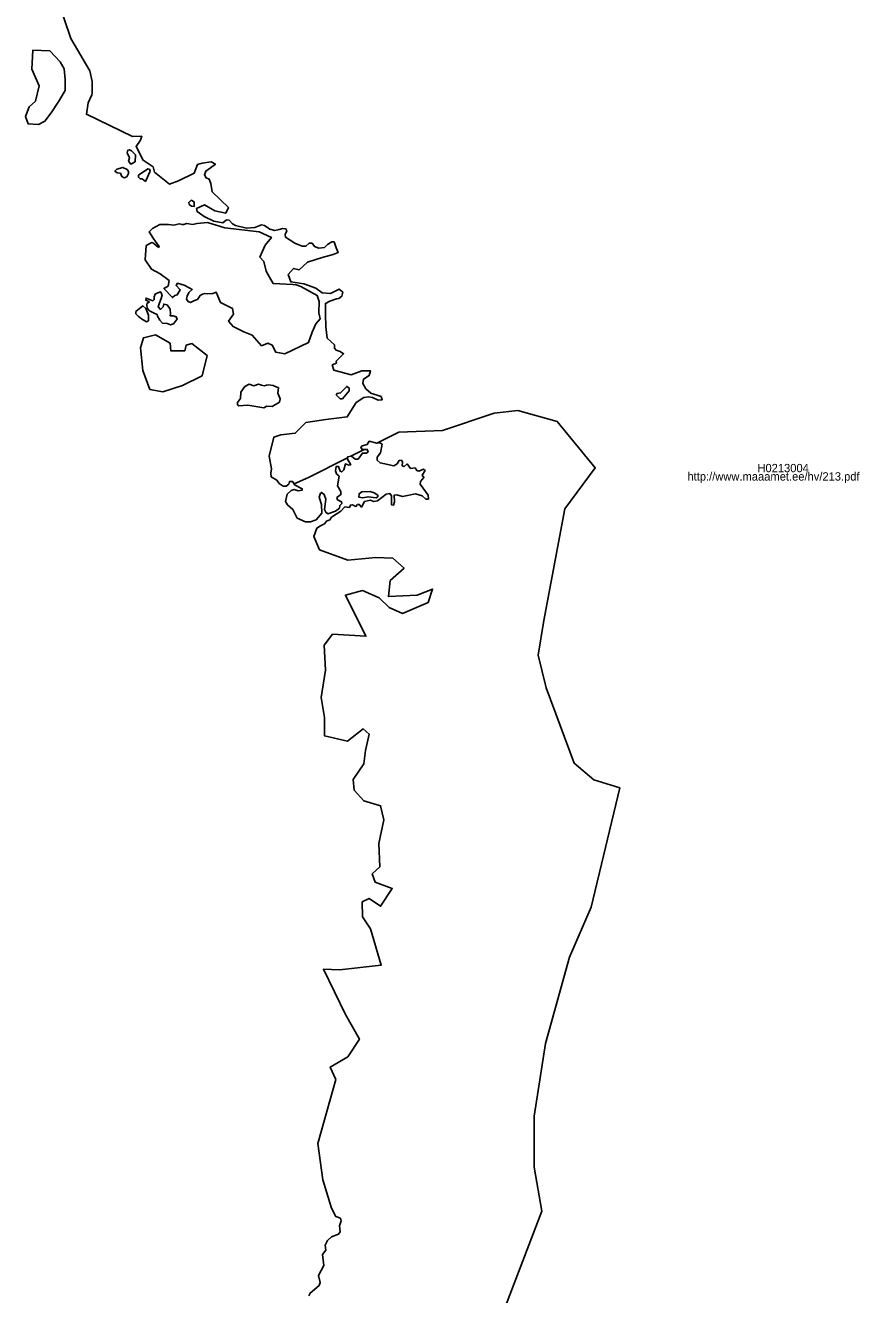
# Model space of a CAD drawing. Extents: x 369010 to 739155, y 6377141 to 6634081.
# Drawn here: x 527309 to 529812, y 6436135 to 6439943 of the extents above; entities that cross this region are included whole.
import ezdxf

# ---------------------------------------------------------------- set-up
doc = ezdxf.new("R2010")
doc.units = 0
for name, color, linetype in [('H_LINK', 7, 'Continuous'), ('H_PIIR', 7, 'Continuous'), ('H_TUNNUS', 7, 'Continuous')]:
    doc.layers.add(name, color=color, linetype=linetype)

msp = doc.modelspace()

# ---------------------------------------------------------------- linework, layer by layer
at = {"layer": 'H_PIIR'}
for points in [[(528684.2701, 6435930.31), (528858.19, 6436385.6599), (528835.72, 6436516.82), (528835.72, 6436670.47), (528869.4301, 6436887.82), (528941.0301, 6437147.3601), (529006.6599, 6437297.3301), (529092.23, 6437655.33), (529014.62, 6437679.2199), (528954.92, 6437728.9901), (528871.34, 6437955.96), (528847.4501, 6438053.52), (528864.37, 6438157.24), (528927.0599, 6438492.7), (529018.6, 6438615.1399), (528904.17, 6438754.51), (528786.7599, 6438787.36), (528715.4001, 6438780.0699), (528559.89, 6438727.6299), (528429.54, 6438722.66), (528363.7136, 6438689.6718), (528340.71, 6438695.2699), (528334.71, 6438685.8), (528318.9401, 6438681.7), (528315.4701, 6438676.3401), (528318.9401, 6438670.34), (528325.3973, 6438670.4737), (528325.3323, 6438670.4412), (528285.5968, 6438650.5333), (528275.7201, 6438648.88), (528274.83, 6438645.1399), (528158.6201, 6438586.9101), (528114.7571, 6438567.5488), (528110.41, 6438574.41), (528101.58, 6438574.41), (528098.74, 6438566.84), (528091.4899, 6438560.8399), (528082.3399, 6438560.8399), (528070.03, 6438568.73), (528062.7801, 6438578.1999), (528046.4723, 6438588.2641), (528045.4139, 6438599.9058), (528047.6299, 6438612.2701), (528040.4483, 6438650.1266), (528054.4466, 6438707.9468), (528075.1983, 6438714.8999), (528118.4391, 6438719.4977), (528150.1891, 6438751.2478), (528210.4322, 6438761.0292), (528274.2862, 6438768.186), (528301.5311, 6438811.5729), (528324.5499, 6438826.2573), (528339.102, 6438828.2417), (528350.3468, 6438826.9187), (528367.5448, 6438818.9812), (528379.4511, 6438819.6427), (528376.1438, 6438829.5646), (528345.7166, 6438839.4865), (528329.8527, 6438853.01), (528321.3326, 6438868.4701), (528323.227, 6438881.8199), (528340.4249, 6438892.4032), (528344.3937, 6438906.9554), (528317.9353, 6438906.2939), (528286.1852, 6438894.3876), (528233.9299, 6438908.9397), (528229.2997, 6438924.1533), (528241.97, 6438929.6901), (528241.34, 6438935.3699), (528263.6956, 6438957.8877), (528252.9549, 6438964.6424), (528241.0199, 6438968.8199), (528235.98, 6438975.1299), (528236.29, 6438984.28), (528214.0861, 6439004.8514), (528210.1174, 6439038.5858), (528208.7945, 6439076.289), (528208.7945, 6439108.7006), (528222.6851, 6439115.3151), (528241.97, 6439122.48), (528249.1435, 6439123.9141), (528257.7425, 6439130.5287), (528261.0498, 6439143.0965), (528250.4664, 6439151.6954), (528224.008, 6439138.4662), (528199.534, 6439141.1121), (528180.3517, 6439155.0027), (528143.86, 6439167.6), (528104.9453, 6439173.5236), (528097.6692, 6439196.0132), (528112.8828, 6439213.8726), (528130.0808, 6439209.2424), (528154.9, 6439232.27), (528199.4723, 6439247.1313), (528232.607, 6439255.5446), (528247.1591, 6439261.4977), (528241.34, 6439276.13), (528234.7101, 6439293.49), (528228.09, 6439294.12), (528214.7476, 6439285.3103), (528206.1486, 6439276.7113), (528188.97, 6439274.24), (528176.03, 6439279.9201), (528168.78, 6439289.38), (528160.2601, 6439290.02), (528150.4801, 6439280.55), (528139.4399, 6439280.8699), (528117.6701, 6439289.38), (528089.59, 6439307.37), (528088, 6439315.5799), (528092.7299, 6439326.94), (528090.5301, 6439332.62), (528081.38, 6439333.88), (528070.02, 6439331.04), (528057.0901, 6439327.57), (528041.9399, 6439331.36), (528026.17, 6439342.4), (528016.7001, 6439344.9299), (527997.14, 6439336.4101), (527972.54, 6439335.1499), (527939.41, 6439342.4), (527929.64, 6439347.4401), (527919.86, 6439358.49), (527911.98, 6439360.0701), (527900.93, 6439350.9201), (527874.43, 6439355.9599), (527845.09, 6439370.16), (527823.64, 6439384.68), (527822.38, 6439393.5101), (527846.513, 6439404.9242), (527876.9402, 6439386.4034), (527910.0131, 6439379.7888), (527917.9507, 6439396.9867), (527869.0026, 6439443.9504), (527864.65, 6439468.92), (527860.55, 6439481.8501), (527851.4, 6439485.64), (527846.04, 6439494.4699), (527849.8203, 6439506.1276), (527863.711, 6439515.388), (527878.9245, 6439526.6328), (527865.6953, 6439533.9089), (527839.237, 6439529.9401), (527824.6848, 6439525.3099), (527815.4244, 6439499.513), (527767.7993, 6439476.3619), (527741.3409, 6439467.1014), (527695.7002, 6439502.8203), (527691.7315, 6439518.6953), (527661.9658, 6439538.5391), (527640.7991, 6439579.5496), (527654.0283, 6439598.7319), (527657.997, 6439610.6382), (527630.2157, 6439609.9767), (527491.9706, 6439676.7842), (527496.9824, 6439711.1537), (527507.8965, 6439734.3048), (527508.8886, 6439740.9194), (527509.2194, 6439753.4871), (527508.5579, 6439763.0783), (527508.5579, 6439774.6539), (527502.3434, 6439806.56), (527445.1933, 6439903.3977), (527403.9182, 6440025.6355)], [(528158.94, 6436131.08), (528163.2101, 6436139.62), (528190.02, 6436162.17), (528193.6799, 6436171.31), (528188.4999, 6436191.7299), (528203.73, 6436222.2), (528200.39, 6436254.8201), (528209.8399, 6436268.5299), (528208.01, 6436283.16), (528215.0199, 6436296.8701), (528226.9, 6436307.8401), (528248.5401, 6436316.68), (528253.41, 6436322.7699), (528251.58, 6436341.3601), (528256.46, 6436356.6), (528254.02, 6436363.91), (528239.7, 6436369.09), (528227.51, 6436394.3901), (528201.0598, 6436479.4249), (528186.1725, 6436588.0101), (528240.1477, 6436780.6271), (528223.2143, 6436817.6689), (528276.1311, 6436848.3606), (528310.7134, 6436901.0461), (528268.7227, 6436975.3609), (528203.1059, 6437110.8278), (528250.731, 6437109.7695), (528376.6729, 6437123.5278), (528343.8645, 6437232.5364), (528320.5811, 6437268.5198), (528319.5228, 6437312.9699), (528340.6895, 6437323.5532), (528374.5563, 6437300.2699), (528409.4813, 6437353.1866), (528358.6812, 6437372.2367), (528349.609, 6437397.794), (528372.4396, 6437418.8034), (528369.2646, 6437488.6536), (528384.0813, 6437559.562), (528374.5563, 6437601.8955), (528323.7562, 6437616.7122), (528295.1811, 6437648.4622), (528292.3799, 6437680.09), (528324.1074, 6437726.9742), (528329.0478, 6437766.9958), (528340.6895, 6437816.7376), (528322.2867, 6437832.1098), (528275.0727, 6437795.5708), (528206.2809, 6437811.4459), (528206.2809, 6437866.4793), (528195.6976, 6437926.8044), (528209.4559, 6438008.2963), (528205.2226, 6438083.4381), (528230.6226, 6438116.2465), (528330.4599, 6438110.2899), (528268.7227, 6438233.7217), (528320.5811, 6438247.4801), (528370.3229, 6438225.255), (528399.9563, 6438196.68), (528440.1731, 6438178.6883), (528517.4315, 6438211.4967), (528530.49, 6438251.6601), (528484.6231, 6438233.7217), (528397.8396, 6438229.4884), (528403.1313, 6438277.1135), (528444.8116, 6438314.9725), (528411.2199, 6438344.73), (528359.838, 6438346.7819), (528276.1311, 6438338.4969), (528191.4642, 6438369.1887), (528174.5999, 6438409.7299), (528183.4401, 6438434.6501), (528194.6392, 6438441.1555), (528206.4701, 6438447.9101), (528212.1499, 6438455.48), (528222.5599, 6438459.8999), (528227.6, 6438467.4701), (528254.74, 6438485.14), (528266.72, 6438498.39), (528280.9201, 6438496.1899), (528284.08, 6438503.7599), (528290.0699, 6438504.3901), (528300.4801, 6438499.6599), (528305.53, 6438505.34), (528310.58, 6438505.97), (528317.2001, 6438497.76), (528326.67, 6438514.1699), (528343.39, 6438518.2701), (528354.1199, 6438514.1699), (528364.84, 6438516.3799), (528391.6501, 6438536.56), (528402.38, 6438538.15), (528406.8, 6438531.5201), (528406.8, 6438505.0201), (528413.42, 6438503.7599), (528416.58, 6438513.5399), (528415.63, 6438533.7299), (528423.52, 6438534.68), (528439.93, 6438529.31), (528479.68, 6438537.8299), (528499.24, 6438531.21), (528509.9601, 6438521.7401), (528518.17, 6438522.06), (528517.22, 6438533.09), (528492.93, 6438566.54), (528493.8701, 6438575.06), (528504.28, 6438586.1), (528499.24, 6438593.36), (528508.0699, 6438607.24), (528503.0201, 6438611.34), (528488.83, 6438605.9801), (528483.15, 6438607.5599), (528478.0999, 6438615.1299), (528464.53, 6438613.87), (528454.12, 6438627.12), (528444.97, 6438619.2301), (528439.6101, 6438621.76), (528440.24, 6438633.75), (528436.77, 6438638.48), (528430.46, 6438637.85), (528423.8299, 6438627.44), (528414.6899, 6438621.4399), (528373.04, 6438630.28), (528363.8899, 6438638.48), (528363.8899, 6438647.63), (528373.99, 6438660.2501), (528379.67, 6438686.44), (528372.72, 6438690.86), (528364.0501, 6438689.5901), (528363.7136, 6438689.6718), (528429.54, 6438722.66), (528559.89, 6438727.6299), (528715.4001, 6438780.0699), (528786.7599, 6438787.36), (528904.17, 6438754.51), (529018.6, 6438615.1399), (528927.0599, 6438492.7), (528864.37, 6438157.24), (528847.4501, 6438053.52), (528871.34, 6437955.96), (528954.92, 6437728.9901), (529014.62, 6437679.2199), (529092.23, 6437655.33), (529006.6599, 6437297.3301), (528941.0301, 6437147.3601), (528869.4301, 6436887.82), (528835.72, 6436670.47), (528835.72, 6436516.82), (528858.19, 6436385.6599), (528684.2701, 6435930.31)]]:
    msp.add_lwpolyline(points, dxfattribs=at)
for points in [[(527327.718, 6439811.3225), (527330.893, 6439868.4726), (527381.6931, 6439866.8851), (527413.4432, 6439833.5476), (527424.5557, 6439812.91), (527427.7307, 6439781.16), (527427.7307, 6439747.8224), (527408.6807, 6439716.0723), (527386.4556, 6439681.1473), (527367.4056, 6439655.7472), (527348.3556, 6439646.2222), (527316.6055, 6439647.8097), (527308.668, 6439670.0347), (527319.7805, 6439698.6098), (527338.8305, 6439716.0723), (527349.9431, 6439762.1099)], [(527638.3695, 6439533.7878), (527624.8801, 6439526.93), (527618.5701, 6439535.4401), (527620.7699, 6439545.54), (527614.15, 6439561), (527615.73, 6439568.58), (527620.7699, 6439570.1501), (527627.0799, 6439566.37), (527638.9069, 6439554.3634)], [(527612.89, 6439489.06), (527605, 6439486.22), (527598.06, 6439489.3801), (527593.6399, 6439500.11), (527583.8601, 6439501.05), (527576.9199, 6439505.78), (527582.92, 6439512.1), (527600.5799, 6439517.14), (527613.8299, 6439510.5199), (527618.25, 6439504.52), (527618.5701, 6439498.84)], [(527683.24, 6439505.78), (527668.7301, 6439475.18), (527659.26, 6439482.75), (527652.95, 6439482.75), (527647.9101, 6439488.1199), (527647.9101, 6439493.48), (527676.3, 6439512.4101), (527681.03, 6439511.46)], [(527814.763, 6439413.5232), (527815.2601, 6439400.08), (527807.37, 6439400.3999), (527800.43, 6439406.0799), (527798.85, 6439412.0701), (527805.79, 6439418.7)], [(527855.3766, 6439351.6547), (527907.4, 6439335.7299), (528010.3566, 6439323.6749), (528046.7369, 6439307.1384), (528028.216, 6439283.3259), (528012.3409, 6439247.6071), (528024.2472, 6439234.3779), (528031.5233, 6439205.2737), (528041.17, 6439187.4399), (528052.0285, 6439168.8934), (528111.38, 6439165.6701), (528120.8203, 6439164.9246), (528134.73, 6439159.3601), (528183.78, 6439132.86), (528190.09, 6439114.55), (528188.83, 6439081.11), (528192.93, 6439063.12), (528179.9901, 6439047.66), (528169.27, 6439022.74), (528158.5235, 6438991.6222), (528087.0859, 6438957.8877), (528059.966, 6438962.518), (528049.3827, 6438983.6847), (528036.1535, 6438989.6378), (528017.6326, 6438981.7003), (527989.1899, 6439014.1118), (527964.0544, 6439023.3723), (527931.6429, 6439039.2473), (527918.4137, 6439055.7838), (527932.9658, 6439076.9505), (527930.32, 6439094.1484), (527894.6011, 6439111.3464), (527886.0022, 6439130.5287), (527881.3719, 6439142.435), (527870.79, 6439139.1701), (527856.2365, 6439137.8048), (527847.4391, 6439138.9293), (527840.3614, 6439137.1433), (527832.6627, 6439133.0328), (527824.6848, 6439120.673), (527816.4827, 6439117.498), (527803.7827, 6439111.6771), (527796.7051, 6439114.6537), (527792.0699, 6439121.8101), (527794.6, 6439130.64), (527799.5494, 6439142.1043), (527809.6036, 6439150.3064), (527802.4598, 6439154.8043), (527784.9973, 6439163.271), (527765.4181, 6439169.3564), (527760.9201, 6439163.0064), (527773.3556, 6439149.7772), (527764.3597, 6439134.4313), (527756.6868, 6439133.1084), (527749.8076, 6439126.2292), (527724.4076, 6439154.0105), (527737.3722, 6439161.1543), (527740.2826, 6439177.2939), (527713.0305, 6439197.9315), (527686.8367, 6439211.4252), (527667.7866, 6439240.0003), (527670.697, 6439282.3337), (527687.895, 6439291.3296), (527693.2085, 6439289.3169), (527707.7388, 6439276.7774), (527709.982, 6439279.406), (527699.48, 6439294.41), (527692.1283, 6439305.0879), (527679.9575, 6439323.3442), (527690.17, 6439333.23), (527712.26, 6439345.85), (527738.13, 6439345.85), (527754.041, 6439343.9818), (527770.4452, 6439348.2151), (527778.9118, 6439345.3047), (527783.6743, 6439345.3047), (527791.6119, 6439348.4797), (527799.0202, 6439347.6859), (527810.21, 6439346.1599), (527823.8911, 6439349.0088)], [(527716.2055, 6439124.1126), (527711.443, 6439111.148), (527707.4742, 6439098.9771), (527713.8242, 6439090.775), (527722.2909, 6439098.7125), (527723.8784, 6439107.1792), (527733.9326, 6439104.7979), (527742.6638, 6439091.3042), (527744.2514, 6439078.075), (527742.6638, 6439071.725), (527751.9243, 6439071.1958), (527761.4493, 6439068.5499), (527763.8306, 6439061.6708), (527759.068, 6439055.5853), (527753.5118, 6439047.3832), (527743.9868, 6439044.2082), (527733.9326, 6439048.4416), (527720.4388, 6439049.4999), (527712.2367, 6439058.2312), (527705.0929, 6439070.402), (527704.2992, 6439075.4291), (527696.6263, 6439079.1333), (527681.2804, 6439086.8062), (527674.1366, 6439094.7438), (527672.8137, 6439105.0625), (527674.4012, 6439110.0896), (527680.2221, 6439112.7355), (527678.6346, 6439115.1167), (527669.6387, 6439119.0855), (527670.9616, 6439125.1709), (527691.3346, 6439116.7042), (527695.3033, 6439120.673), (527695.3033, 6439128.6105), (527697.9492, 6439136.8126), (527706.1513, 6439141.0459), (527713.8242, 6439143.6918), (527719.1159, 6439134.6959)], [(527677.8408, 6439056.3791), (527671.7554, 6439053.4687), (527657.2033, 6439062.4645), (527647.4137, 6439070.402), (527640.5345, 6439077.8104), (527640.5345, 6439084.425), (527660.9074, 6439101.3583), (527670.1679, 6439093.6854), (527678.37, 6439074.1062)], [(527742.73, 6438989.3732), (527744.8467, 6438967.1482), (527787.1801, 6438967.1482), (527791.4134, 6438984.0816), (527808.3468, 6438988.3149), (527853.8552, 6438952.3315), (527839.0385, 6438892.0064), (527779.7717, 6438862.373), (527721.5633, 6438843.3229), (527682.4049, 6438850.7313), (527661.2382, 6438907.8814), (527653.8298, 6438975.6149), (527663.05, 6439005.99), (527699.3382, 6439014.7733)], [(528017.6326, 6438863.299), (528024.9087, 6438861.9761), (528031.86, 6438863.3701), (528038.8, 6438864.3199), (528052.0285, 6438862.6376), (528063.09, 6438857.69), (528068.14, 6438856.4301), (528066.56, 6438839.7001), (528073.1901, 6438822.9801), (528071.2999, 6438812.88), (528049.5301, 6438799.3201), (528032.8101, 6438800.8899), (528024.29, 6438795.8501), (527975.7101, 6438803.7299), (527949.21, 6438801.21), (527944.79, 6438805.0001), (527945.42, 6438811.3099), (527954.57, 6438823.61), (527955.2, 6438842.23), (527967.4999, 6438859.9001), (527980.12, 6438866.52), (527993.9999, 6438862.1101), (528007.8799, 6438866.84)], [(528260.25, 6438823.03), (528253.6199, 6438822.72), (528241.6401, 6438834.71), (528243.8399, 6438839.1201), (528254.2599, 6438840.38), (528272.8701, 6438859.95), (528280.12, 6438854.9), (528279.8101, 6438846.38)], [(528274.8343, 6438645.1422), (528274.4499, 6438643.5201), (528284.8699, 6438624.59), (528279.1901, 6438623.3301), (528269.09, 6438627.11), (528264.0399, 6438610.0701), (528258.05, 6438603.45), (528253, 6438605.3399), (528248.5801, 6438619.54), (528241.0099, 6438619.54), (528238.8001, 6438606.92), (528241.96, 6438597.7699), (528250.48, 6438590.2), (528244.8, 6438561.4799), (528255.21, 6438544.44), (528255.5301, 6438535.29), (528243.54, 6438526.7799), (528245.43, 6438519.8299), (528257.42, 6438513.84), (528257.7399, 6438508.16), (528252.6901, 6438502.8), (528251.4301, 6438494.91), (528239.12, 6438485.13), (528216.41, 6438477.8701), (528209.7799, 6438482.29), (528206.3099, 6438490.4899), (528210.1, 6438521.41), (528205.3701, 6438535.6101), (528197.48, 6438541.9201), (528193.6899, 6438539.4), (528189.91, 6438527.09), (528197.1599, 6438505.95), (528198.11, 6438479.76), (528180.76, 6438459.8799), (528164.04, 6438453.89), (528149.2099, 6438453.5699), (528124.6001, 6438464.93), (528111.35, 6438490.8), (528094.9599, 6438504.3599), (528089.2799, 6438514.7701), (528094.33, 6438536.23), (528105.68, 6438547.9), (528114.83, 6438550.74), (528127.4501, 6438546.33), (528138.8099, 6438548.2199), (528139.4399, 6438552.64), (528116.4101, 6438564.9399), (528114.7601, 6438567.55), (528158.6201, 6438586.9101)], [(528325.3973, 6438670.4737), (528334.3999, 6438670.6601), (528336.9201, 6438663.7101), (528331.87, 6438659.6101), (528319.88, 6438659.6101), (528306.95, 6438641.94), (528298.43, 6438641.31), (528287.07, 6438650.78), (528285.5968, 6438650.5333), (528325.3323, 6438670.4412)], [(528361.0299, 6438525.7901), (528336.7399, 6438528.95), (528320.97, 6438525.48), (528309.3, 6438527.3699), (528309.93, 6438537.7799), (528318.13, 6438543.1501), (528342.74, 6438544.41), (528354.7201, 6438540.6199), (528365.7701, 6438533.6799), (528365.7701, 6438528.95)]]:
    msp.add_lwpolyline(points, close=True, dxfattribs=at)

# ---------------------------------------------------------------- texts
at = {"layer": 'H_LINK'}
msp.add_text('http://www.maaamet.ee/hv/213.pdf', height=25, rotation=0, dxfattribs=at).set_placement((529295.2085, 6438577.353))
at = {"layer": 'H_TUNNUS'}
msp.add_text('H0213004', height=25, rotation=0, dxfattribs=at).set_placement((529505.1877, 6438602.353))

doc.saveas('drawing.dxf')
